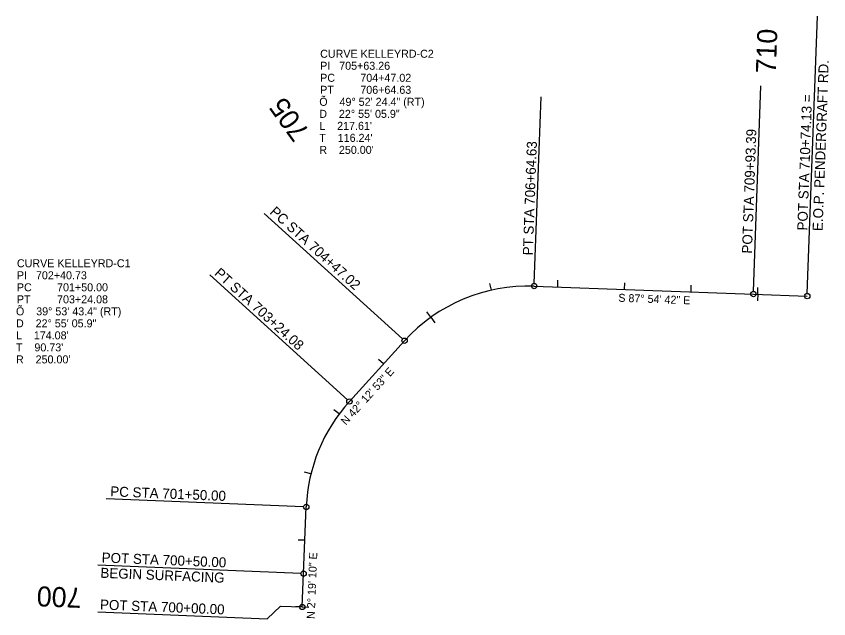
# Model space of a CAD drawing. Extents: x 2819977 to 2827606, y 113942 to 150283.
# Drawn here: x 2825066 to 2826284, y 129358 to 130260 of the extents above; entities that cross this region are included whole.
import ezdxf

# ---------------------------------------------------------------- set-up
doc = ezdxf.new("R2010")
doc.units = 0
for name, color, linetype in [('Level 63', 7, 'Continuous'), ('Roadway-Signs', 7, 'Continuous'), ('Roadway-Walls', 7, 'Continuous'), ('Utility-Power', 7, 'Continuous')]:
    doc.layers.add(name, color=color, linetype=linetype)

msp = doc.modelspace()

# ---------------------------------------------------------------- linework, layer by layer
at = {"layer": 'Level 63'}
for p, q in [((2826251.6, 129845), (2826266.7, 130260.3)), ((2826170.9, 129848), (2826182.1, 130155.8)), ((2825842.4, 129860), (2825852.6, 130139.5)), ((2825645, 129776.8), (2825437.5, 129965)), ((2825562.4, 129685.7), (2825356, 129873)), ((2825496.7, 129525.4), (2825200.8, 129537.3)), ((2825492.7, 129425.4), (2825188.5, 129437.8))]:
    msp.add_line(p, q, dxfattribs=at)
msp.add_lwpolyline([(2825188.3, 129367.9), (2825442.2, 129357.6), (2825462.1, 129376.6), (2825494.7, 129375.3)], dxfattribs=at)
for centre in [(2825842.2, 129856), (2826170.8, 129844), (2826251.5, 129841), (2825648, 129774.1), (2825565.4, 129683.1), (2825500.7, 129525.2), (2825496.7, 129425.3), (2825494.7, 129375.3)]:
    msp.add_circle(centre, 4, dxfattribs=at)
at = {"layer": 'Utility-Power'}
for p, q in [((2825877.6, 129854.7), (2825877.9, 129864.7)), ((2825778.1, 129850), (2825775.9, 129859.7)), ((2825842.2, 129856), (2826170.8, 129844)), ((2825977.5, 129851), (2825977.9, 129861)), ((2826077.4, 129847.4), (2826077.8, 129857.4)), ((2826177.4, 129843.7), (2826177.7, 129853.7)), ((2826170.8, 129844), (2826251.5, 129841)), ((2826177.4, 129843.7), (2826177, 129833.7)), ((2825687.4, 129809.3), (2825681.6, 129817.4)), ((2825687.4, 129809.3), (2825693.3, 129801.2)), ((2825565.4, 129683.1), (2825648, 129774.1)), ((2825616.4, 129739.3), (2825609, 129746)), ((2825550.1, 129664.5), (2825542, 129670.4)), ((2825507.7, 129574.6), (2825498, 129577)), ((2825496.7, 129425.3), (2825500.7, 129525.2)), ((2825498.7, 129475.2), (2825488.7, 129475.6)), ((2825494.7, 129375.3), (2825496.7, 129425.3)), ((2825494.7, 129375.3), (2825484.7, 129375.7)), ((2825494.7, 129375.3), (2825504.6, 129374.9))]:
    msp.add_line(p, q, dxfattribs=at)
for centre, start, end in [((2825833.1, 129606.1), 87.9117, 137.7851), ((2825750.5, 129515.1), 137.7851, 177.6805)]:
    msp.add_arc(centre, 250, start, end, dxfattribs=at)

# ---------------------------------------------------------------- texts
at = {"layer": 'Level 63'}
for s, rotation, p in [('E.O.P. PENDERGRAFT RD.', 87.9117, (2826274.5, 129938.2)), ('POT STA 710+74.13 =', 87.9117, (2826251.5, 129939.1)), ('POT STA 709+93.39', 87.9117, (2826168.6, 129904.5)), ('PT STA 706+64.63', 87.9117, (2825840.2, 129901.8)), ('PC STA 704+47.02', 317.7851, (2825445, 129965.6)), ('PT STA 703+24.08', 317.7851, (2825361.8, 129873.7)), ('PC STA 701+50.00', 357.6805, (2825206.7, 129541.1)), ('POT STA 700+50.00', 357.6805, (2825193.8, 129442)), ('BEGIN SURFACING', 357.6805, (2825191.9, 129419.1)), ('POT STA 700+00.00', 357.6805, (2825191.3, 129371.6))]:
    msp.add_text(s, height=15, rotation=rotation, dxfattribs=at).set_placement(p)
at = {"layer": 'Roadway-Signs'}
for s, rotation, p in [('S 87%%d 54\' 42" E', 357.9117, (2825968.2, 129832.6)), ('N 42%%d 12\' 53" E', 47.7851, (2825560.2, 129646.8)), ('N 2%%d 19\' 10" E', 87.6805, (2825513.2, 129357.1))]:
    msp.add_text(s, height=12, rotation=rotation, dxfattribs=at).set_placement(p)
at = {"layer": 'Roadway-Walls'}
for s, p in [('CURVE KELLEYRD-C2', (2825521.5, 130198.1)), ('PI   705+63.26', (2825521.5, 130180.1)), ('PC', (2825521.5, 130162.1)), ('704+47.02', (2825581.7, 130162.1)), ('PT', (2825521.5, 130144.1)), ('706+64.63', (2825581.7, 130144.1)), ('Õ    49%%d 52\' 24.4" (RT)', (2825520.2, 130126.1)), ('D    22%%d 55\' 05.9"', (2825520.2, 130108.1)), ("L    217.61'", (2825520.2, 130090.1)), ("T    116.24'", (2825520.2, 130072.1)), ("R    250.00'", (2825520.2, 130054.1)), ('CURVE KELLEYRD-C1', (2825067, 129884.2)), ('PI   702+40.73', (2825067, 129866.2)), ('PC', (2825067, 129848.2)), ('701+50.00', (2825127.2, 129848.2)), ('PT', (2825067, 129830.2)), ('703+24.08', (2825127.2, 129830.2)), ('Õ    39%%d 53\' 43.4" (RT)', (2825065.6, 129812.2)), ('D    22%%d 55\' 05.9"', (2825065.6, 129794.2)), ("L    174.08'", (2825065.6, 129776.2)), ("T    90.73'", (2825065.6, 129758.2)), ("R    250.00'", (2825065.6, 129740.2))]:
    msp.add_text(s, height=12, dxfattribs=at).set_placement(p)
at = {"layer": 'Utility-Power'}
for s, rotation, p in [(' 710', 87.9117, (2826204, 130163)), (' 705', 125.6426, (2825513.2, 130078.1)), (' 700', 177.6805, (2825175.5, 129403.3))]:
    msp.add_text(s, height=30, rotation=rotation, dxfattribs=at).set_placement(p)

doc.saveas('drawing.dxf')
